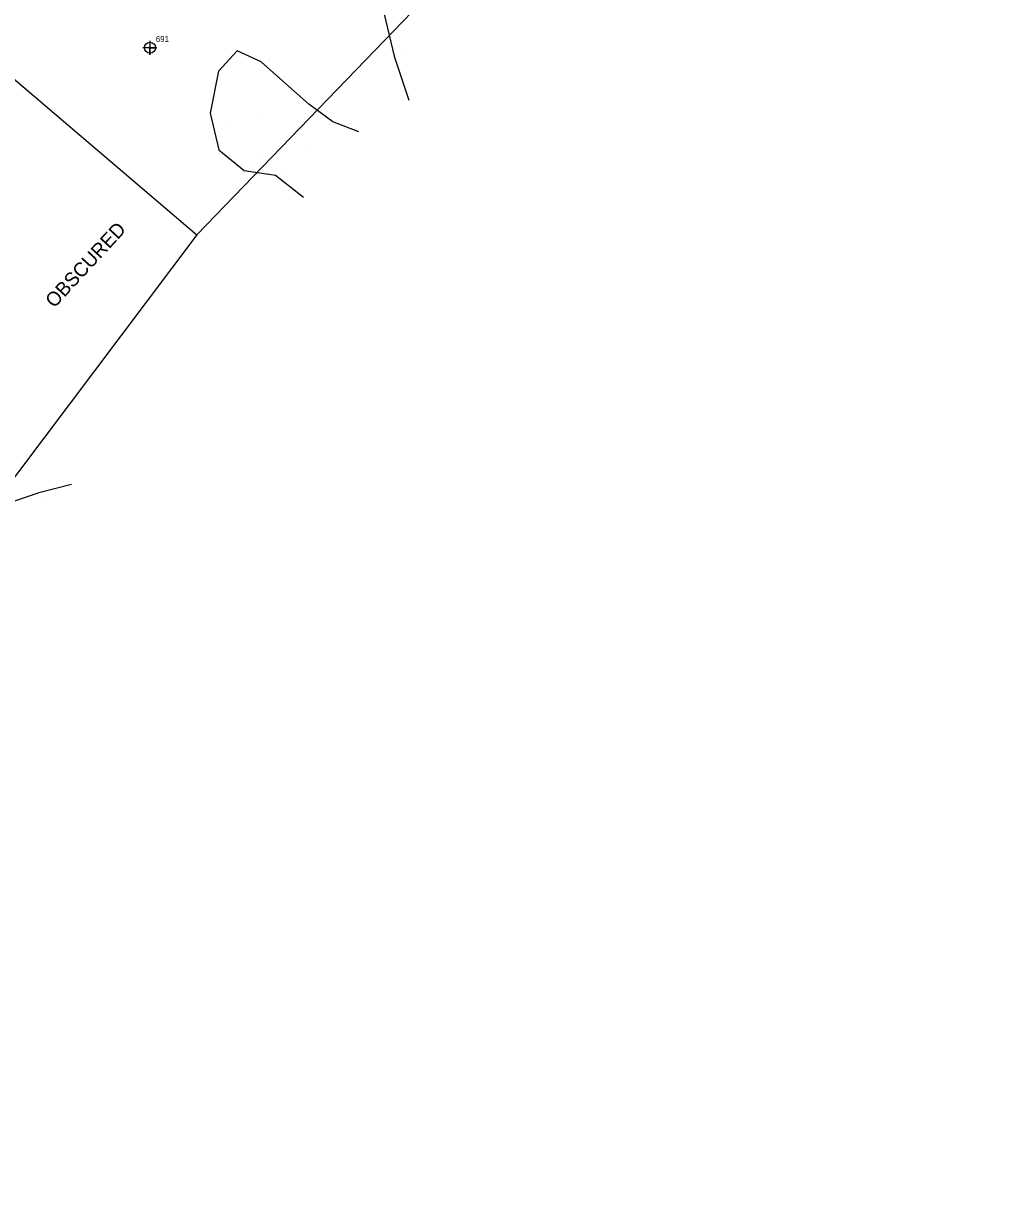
# Model space of a CAD drawing. Extents: x 1497074 to 1501343, y 481943 to 486114.
# Drawn here: x 1499153.8 to 1499565.8, y 484841.1 to 485334 of the extents above; entities that cross this region are included whole.
import ezdxf

# ---------------------------------------------------------------- set-up
doc = ezdxf.new("R2010")
doc.units = 0
for name, color, linetype in [('Exist DTM Regular Point CELL', 7, 'Continuous'), ('Exist DTM Regular Point Cogo Number', 7, 'Continuous'), ('PH Exist DTM Boundary', 7, 'Continuous'), ('PH Exist DTM Obscure Area', 7, 'Continuous'), ('PH Exist DTM Obscure Area Text', 7, 'Continuous'), ('PH Exist DTM Point', 7, 'Continuous')]:
    doc.layers.add(name, color=color, linetype=linetype)

msp = doc.modelspace()

# ---------------------------------------------------------------- linework, layer by layer
at = {"layer": 'Exist DTM Regular Point CELL'}
msp.add_lwpolyline([(1499207.61, 485326.59), (1499207.61, 485320.59), (1499207.61, 485323.59), (1499210.61, 485323.59), (1499204.61, 485323.59)], dxfattribs=at)
msp.add_circle((1499207.61, 485323.59), 2.34, dxfattribs=at)
at = {"layer": 'PH Exist DTM Boundary'}
for points in [[(1498846.5, 485569.16), (1499227.59, 485244.03), (1499565.8, 485594.67), (1499194.3, 485929.74)], [(1498924.23, 484841.06), (1498545.19, 485168.9), (1498846.5, 485569.16), (1499227.59, 485244.03)]]:
    msp.add_lwpolyline(points, close=True, dxfattribs=at)
at = {"layer": 'PH Exist DTM Obscure Area'}
for points in [[(1499149.23, 485468.18), (1499156.41, 485483.23), (1499168.58, 485498.07), (1499183.61, 485514.9), (1499197.34, 485529.91), (1499212.52, 485534.63), (1499222.72, 485529.9), (1499232.31, 485519.64), (1499234.08, 485508.3), (1499229.88, 485495.42), (1499220.2, 485480.12), (1499219.41, 485460.49), (1499225.77, 485441.12), (1499228.02, 485432.48), (1499228.46, 485418.31), (1499232.97, 485402.23), (1499241.35, 485391.01), (1499261.85, 485386.79), (1499278, 485376.9), (1499289.37, 485366.83), (1499301.98, 485354.41), (1499307.09, 485337.87), (1499311.37, 485319.99), (1499317.64, 485301.29)], [(1499174.34, 485137.93), (1499160.4, 485134.34), (1499150.09, 485130.83), (1499139.94, 485137.08), (1499138.98, 485158.83), (1499137.42, 485186.87), (1499131.76, 485212.27), (1499128.15, 485235.71), (1499128.29, 485259.69), (1499129.56, 485280.15), (1499132.29, 485298.2), (1499132.53, 485317.27), (1499132.06, 485333.2)], [(1499296.39, 485287.84), (1499285.35, 485292.16), (1499275.17, 485299.57), (1499265.27, 485308.41), (1499254.93, 485317.65), (1499244.63, 485322.23), (1499236.69, 485313.7), (1499233.18, 485295.78), (1499236.84, 485280.14), (1499247.63, 485271.34), (1499260.96, 485269.4), (1499272.92, 485260.08)]]:
    msp.add_lwpolyline(points, dxfattribs=at)
at = {"layer": 'PH Exist DTM Point'}
for p, q in [((1499317.19, 485321.55), (1499317.19, 485321.55)), ((1499258.46, 485318.56), (1499258.46, 485318.56)), ((1499240.86, 485291.63), (1499240.86, 485291.63)), ((1499255.58, 485295.41), (1499255.58, 485295.41)), ((1499276.47, 485280.89), (1499276.47, 485280.89)), ((1499240.62, 485276.01), (1499240.62, 485276.01)), ((1499253.83, 485278.08), (1499253.83, 485278.08)), ((1499265.64, 485270.22), (1499265.64, 485270.22)), ((1499161.94, 485131.26), (1499161.94, 485131.26))]:
    msp.add_line(p, q, dxfattribs=at)

# ---------------------------------------------------------------- texts
at = {"layer": 'Exist DTM Regular Point Cogo Number'}
msp.add_text('691', height=2.5, dxfattribs=at).set_placement((1499210.11, 485326.09))
at = {"layer": 'PH Exist DTM Obscure Area Text'}
msp.add_text('OBSCURED', height=6, rotation=47.2398, dxfattribs=at).set_placement((1499166.96, 485212.65))

doc.saveas('drawing.dxf')
